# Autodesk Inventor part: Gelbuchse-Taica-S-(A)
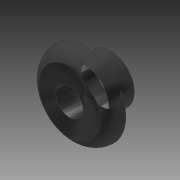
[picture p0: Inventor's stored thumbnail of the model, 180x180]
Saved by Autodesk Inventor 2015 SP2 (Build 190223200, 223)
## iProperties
Created: 2014-11
Part Number: Gelbuchse-Taica-S-(A)
Material: Gummi, Silikon
Document SubType Name: Modeling
Designer: Hübner
Density: 1 g/cm^3
Appearance: Gummi - schwarz - Version 1.1
Author: Hübner
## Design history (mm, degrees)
sketch "Skizze1"
  geometry: C1 r 3.5 at (0, 0); C2 r 6 at (0, 0); 1 further point
  constraints: 2 centre point, 2 coincident
  dimensions: "d0" = 7 diameter of C1; "d1" = 12 diameter of C2
extrude "Extrusion1" new body sketch "Skizze1" distance "d2" = 3.75; taper "d3" = 0 deg
extrude "Extrusion2" join sketch "Skizze1" distance "d4" = 2.25; taper "d5" = 0 deg
sketch "Skizze2"
  geometry: L1 (0, 6)-(-2.25, 6) reference; L2 (0, 6)-(0, -6) reference; L3 (-2.25, 6)-(-2.25, -6) reference; L4 (-2.972, 0)-(0.495, 0) reference; A1 r 2.437 centre (0, 3.563) between (0, 6) and (-2.25, 4.5); 1 further point
  constraints: 2 point on circle, 2 point on line, 1 centre point, 1 end point
  dimensions: "d20" = 4.5 distance from line of A1.end L4
revolve "Umdrehung1" sketch "Skizze2" stored, may be unused: angle "d17" = 90 deg
hole "Bohrung1" diameter "d8" = 4; stored, may be unused: countersink angle "d12" = 90 deg, drill point angle "d14" = 118 deg; dims "d9" = 6, "d10" = 4, "d11" = 2, "d13" = 8, "d18" = 10, "d19" = 10
node "Volumenkörper1"
